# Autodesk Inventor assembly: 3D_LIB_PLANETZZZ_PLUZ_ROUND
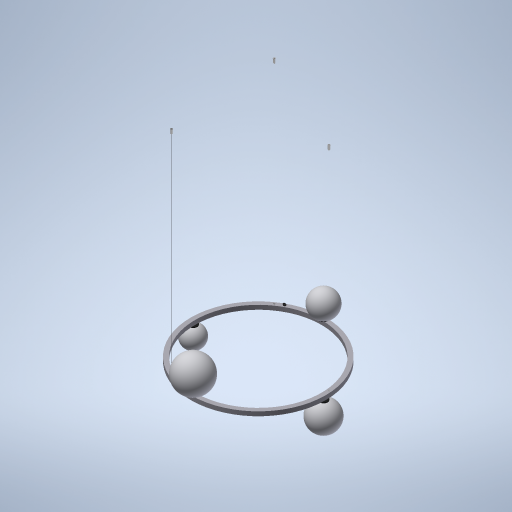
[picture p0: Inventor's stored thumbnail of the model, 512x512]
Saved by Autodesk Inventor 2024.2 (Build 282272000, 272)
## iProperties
Created: 2023-11
Part Number: 3D_LIB_PLANETZZZ_PLUZ_ROUND
Document SubType Name: Assembly
Designer: Manuel
Project: 453 - PLANETZZZ
Description: PLANETZZZ - 950 Assy
Company: DARK
Author: Manuel
Revision Number: v0
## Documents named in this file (12)
- C:\Users\Stage\Desktop\Stage Karsten\armatures\453 - PLANETZZZ\453_KARSTEN\3D_LIB_PLANETZZZ_PLUZ_ROUND.iam
- C:\Users\Stage\Desktop\TUUR\2D en 3D\PLANETZZZ PLUZ\PLANETZZZ PLUZ\453-100.iam
- C:\Users\Stage\Desktop\TUUR\2D en 3D\PLANETZZZ PLUZ\PLANETZZZ PLUZ\PLANETZZZ - Moon dia 150 Assy.iam
- C:\Users\Stage\Desktop\TUUR\2D en 3D\PLANETZZZ PLUZ\PLANETZZZ PLUZ\PLANETZZZ - Moon dia 180 Assy.iam
- C:\Users\Stage\Desktop\TUUR\2D en 3D\PLANETZZZ PLUZ\PLANETZZZ PLUZ\PLANETZZZ - Moon dia 200 Assy.iam
- C:\Users\Stage\Desktop\TUUR\2D en 3D\PLANETZZZ PLUZ\PLANETZZZ PLUZ\PLANETZZZ - Moon dia 240 Assy.iam
- C:\Users\Stage\Desktop\TUUR\2D en 3D\PLANETZZZ PLUZ\PLANETZZZ PLUZ\190-1000-000001.ipt
- C:\Users\Stage\Desktop\TUUR\2D en 3D\PLANETZZZ PLUZ\PLANETZZZ PLUZ\190-1000-000008.ipt
- C:\Users\Stage\Desktop\TUUR\2D en 3D\PLANETZZZ PLUZ\PLANETZZZ PLUZ\190-1000-000009.ipt
- C:\Users\Stage\Desktop\TUUR\2D en 3D\PLANETZZZ PLUZ\PLANETZZZ PLUZ\190-2012-001500.ipt
- C:\Users\Stage\Desktop\TUUR\2D en 3D\PLANETZZZ PLUZ\PLANETZZZ PLUZ\120-4000-000014.ipt
- C:\Users\Stage\Desktop\TUUR\2D en 3D\PLANETZZZ PLUZ\PLANETZZZ PLUZ\400-031.ipt
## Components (22 placed, 11 different names)
1. 400-031:1 — Mate:2, Mate:3, Mate:4, Mate:7, Mate:8, Mate:9, Mate:10, Mate:25, Mate:26, Flush:4, Mate:29, Mate:30, Mate:31, Mate:32, Mate:33, Mate:34, Mate:35
2. 453-100:1 [sub-assembly] — Mate:9, Mate:10, Mate:32, Mate:38, Mate:39
3. 453-100:2 [sub-assembly] — Mate:33, Mate:34, Mate:35, Mate:42, Mate:43
4. 453-100:3 [sub-assembly] — Mate:2, Mate:7, Mate:8, Mate:40, Mate:41
5. 453-100:5 [sub-assembly] — Mate:3, Mate:4, Mate:31, Mate:36, Mate:37
6. PLANETZZZ - Moon dia 150 Assy:1 [sub-assembly] — Mate:40, Mate:41
7. PLANETZZZ - Moon dia 180 Assy:1 [sub-assembly] — Mate:36, Mate:37
8. PLANETZZZ - Moon dia 200 Assy:1 [sub-assembly] — Mate:38, Mate:39
9. PLANETZZZ - Moon dia 240 Assy:1 [sub-assembly] — Mate:42, Mate:43
10. 120-4000-000014:1 — Mate:29, Mate:30
11. 190-1000-000001:1 — Mate:23, Mate:24
12. Suspension part fixture M10x1 - ø2mm:1 — Mate:25, Mate:26, Mate:27, Mate:28
13. 190-1000-000009:1 — Mate:23, Mate:24, Mate:27, Flush:5
14. 190-2012-001500:1 — Flush:4, Mate:28, Flush:5
15. 190-1000-000001:2
16. Suspension part fixture M10x1 - ø2mm:2
17. 190-1000-000009:2
18. 190-2012-001500:2
19. 190-1000-000001:3
20. Suspension part fixture M10x1 - ø2mm:3
21. 190-1000-000009:3
22. 190-2012-001500:3
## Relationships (30: Mate 28, Flush 2)
- Mate:2: 400-031:1 ↔ 453-100:3
- Mate:3: 400-031:1 ↔ 453-100:5
- Mate:4: 400-031:1 ↔ 453-100:5
- Mate:7: 400-031:1 ↔ 453-100:3
- Mate:8: 400-031:1 ↔ 453-100:3
- Mate:9: 400-031:1 ↔ 453-100:1
- Mate:10: 400-031:1 ↔ 453-100:1
- Mate:23: 190-1000-000001:1 ↔ 190-1000-000009:1
- Mate:24: 190-1000-000001:1 ↔ 190-1000-000009:1
- Mate:25: 400-031:1 ↔ Suspension part fixture M10x1 - ø2mm:1
- Mate:26: 400-031:1 ↔ Suspension part fixture M10x1 - ø2mm:1
- Mate:27: Suspension part fixture M10x1 - ø2mm:1 ↔ 190-1000-000009:1
- Flush:4: 400-031:1 ↔ 190-2012-001500:1
- Mate:28: Suspension part fixture M10x1 - ø2mm:1 ↔ 190-2012-001500:1
- Flush:5: 190-1000-000009:1 ↔ 190-2012-001500:1
- Mate:29: 400-031:1 ↔ 120-4000-000014:1
- Mate:30: 400-031:1 ↔ 120-4000-000014:1
- Mate:31: 400-031:1 ↔ 453-100:5
- Mate:32: 400-031:1 ↔ 453-100:1
- Mate:33: 400-031:1 ↔ 453-100:2
- Mate:34: 400-031:1 ↔ 453-100:2
- Mate:35: 400-031:1 ↔ 453-100:2
- Mate:36: 453-100:5 ↔ PLANETZZZ - Moon dia 180 Assy:1
- Mate:37: 453-100:5 ↔ PLANETZZZ - Moon dia 180 Assy:1
- Mate:38: 453-100:1 ↔ PLANETZZZ - Moon dia 200 Assy:1
- Mate:39: 453-100:1 ↔ PLANETZZZ - Moon dia 200 Assy:1
- Mate:40: 453-100:3 ↔ PLANETZZZ - Moon dia 150 Assy:1
- Mate:41: 453-100:3 ↔ PLANETZZZ - Moon dia 150 Assy:1
- Mate:42: 453-100:2 ↔ PLANETZZZ - Moon dia 240 Assy:1
- Mate:43: 453-100:2 ↔ PLANETZZZ - Moon dia 240 Assy:1
